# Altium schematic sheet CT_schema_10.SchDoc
size 741 x 377 mm
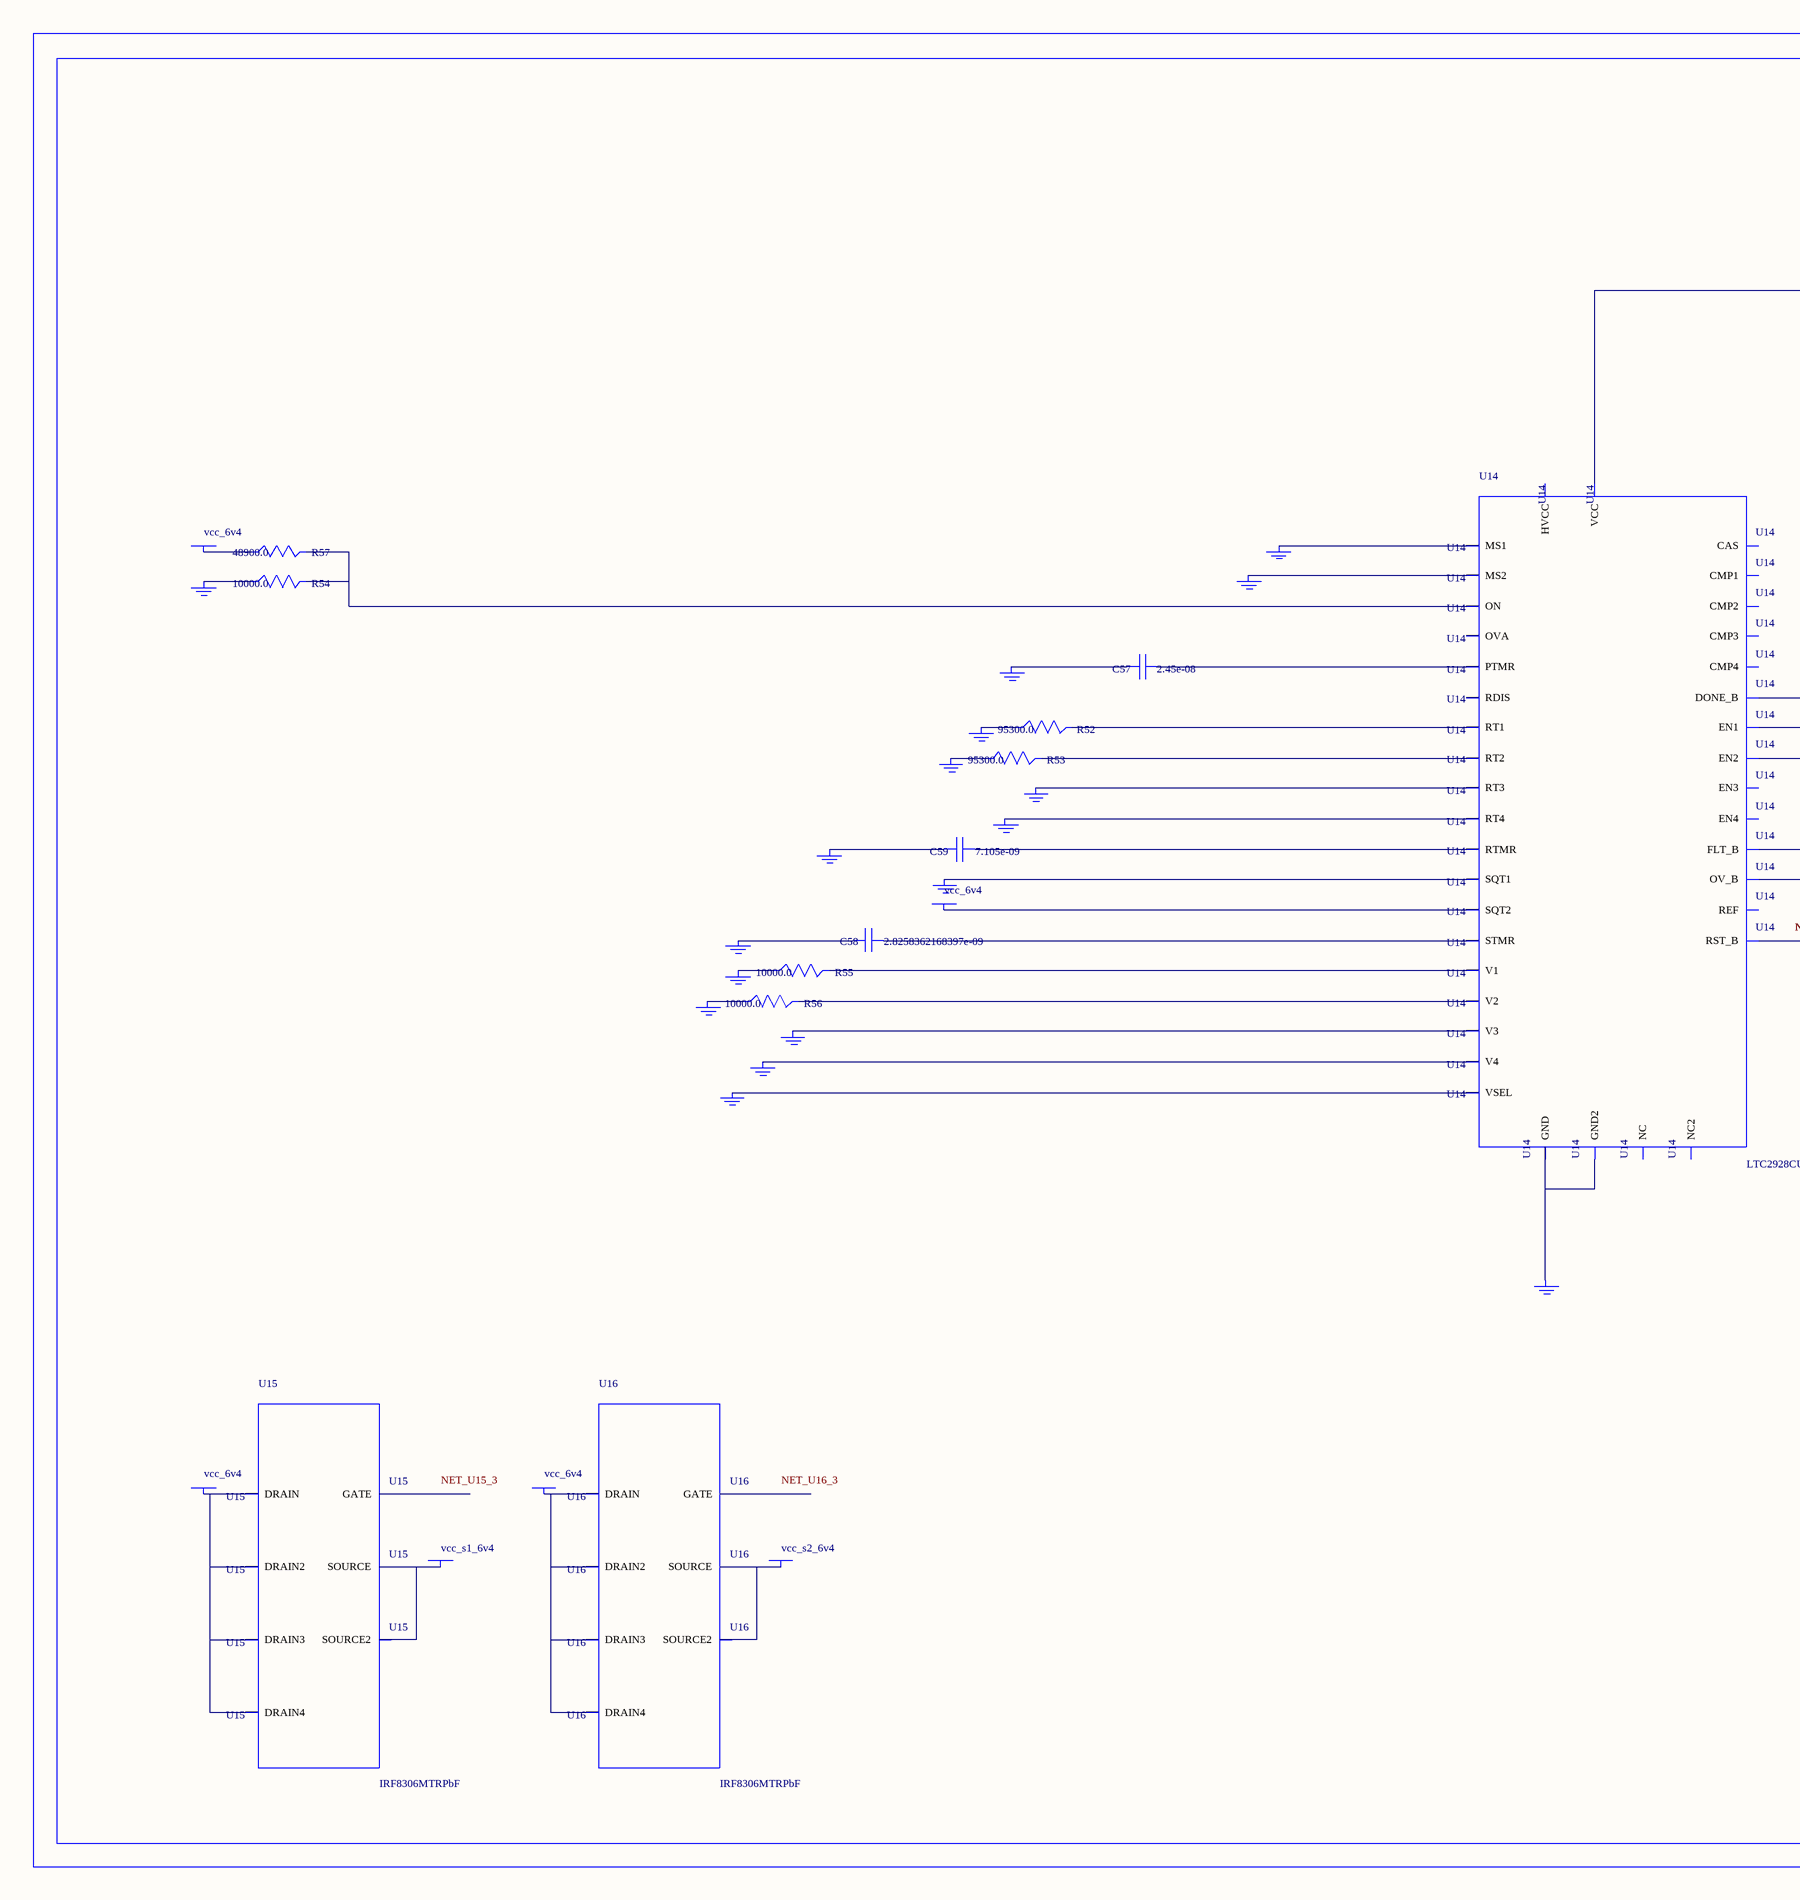
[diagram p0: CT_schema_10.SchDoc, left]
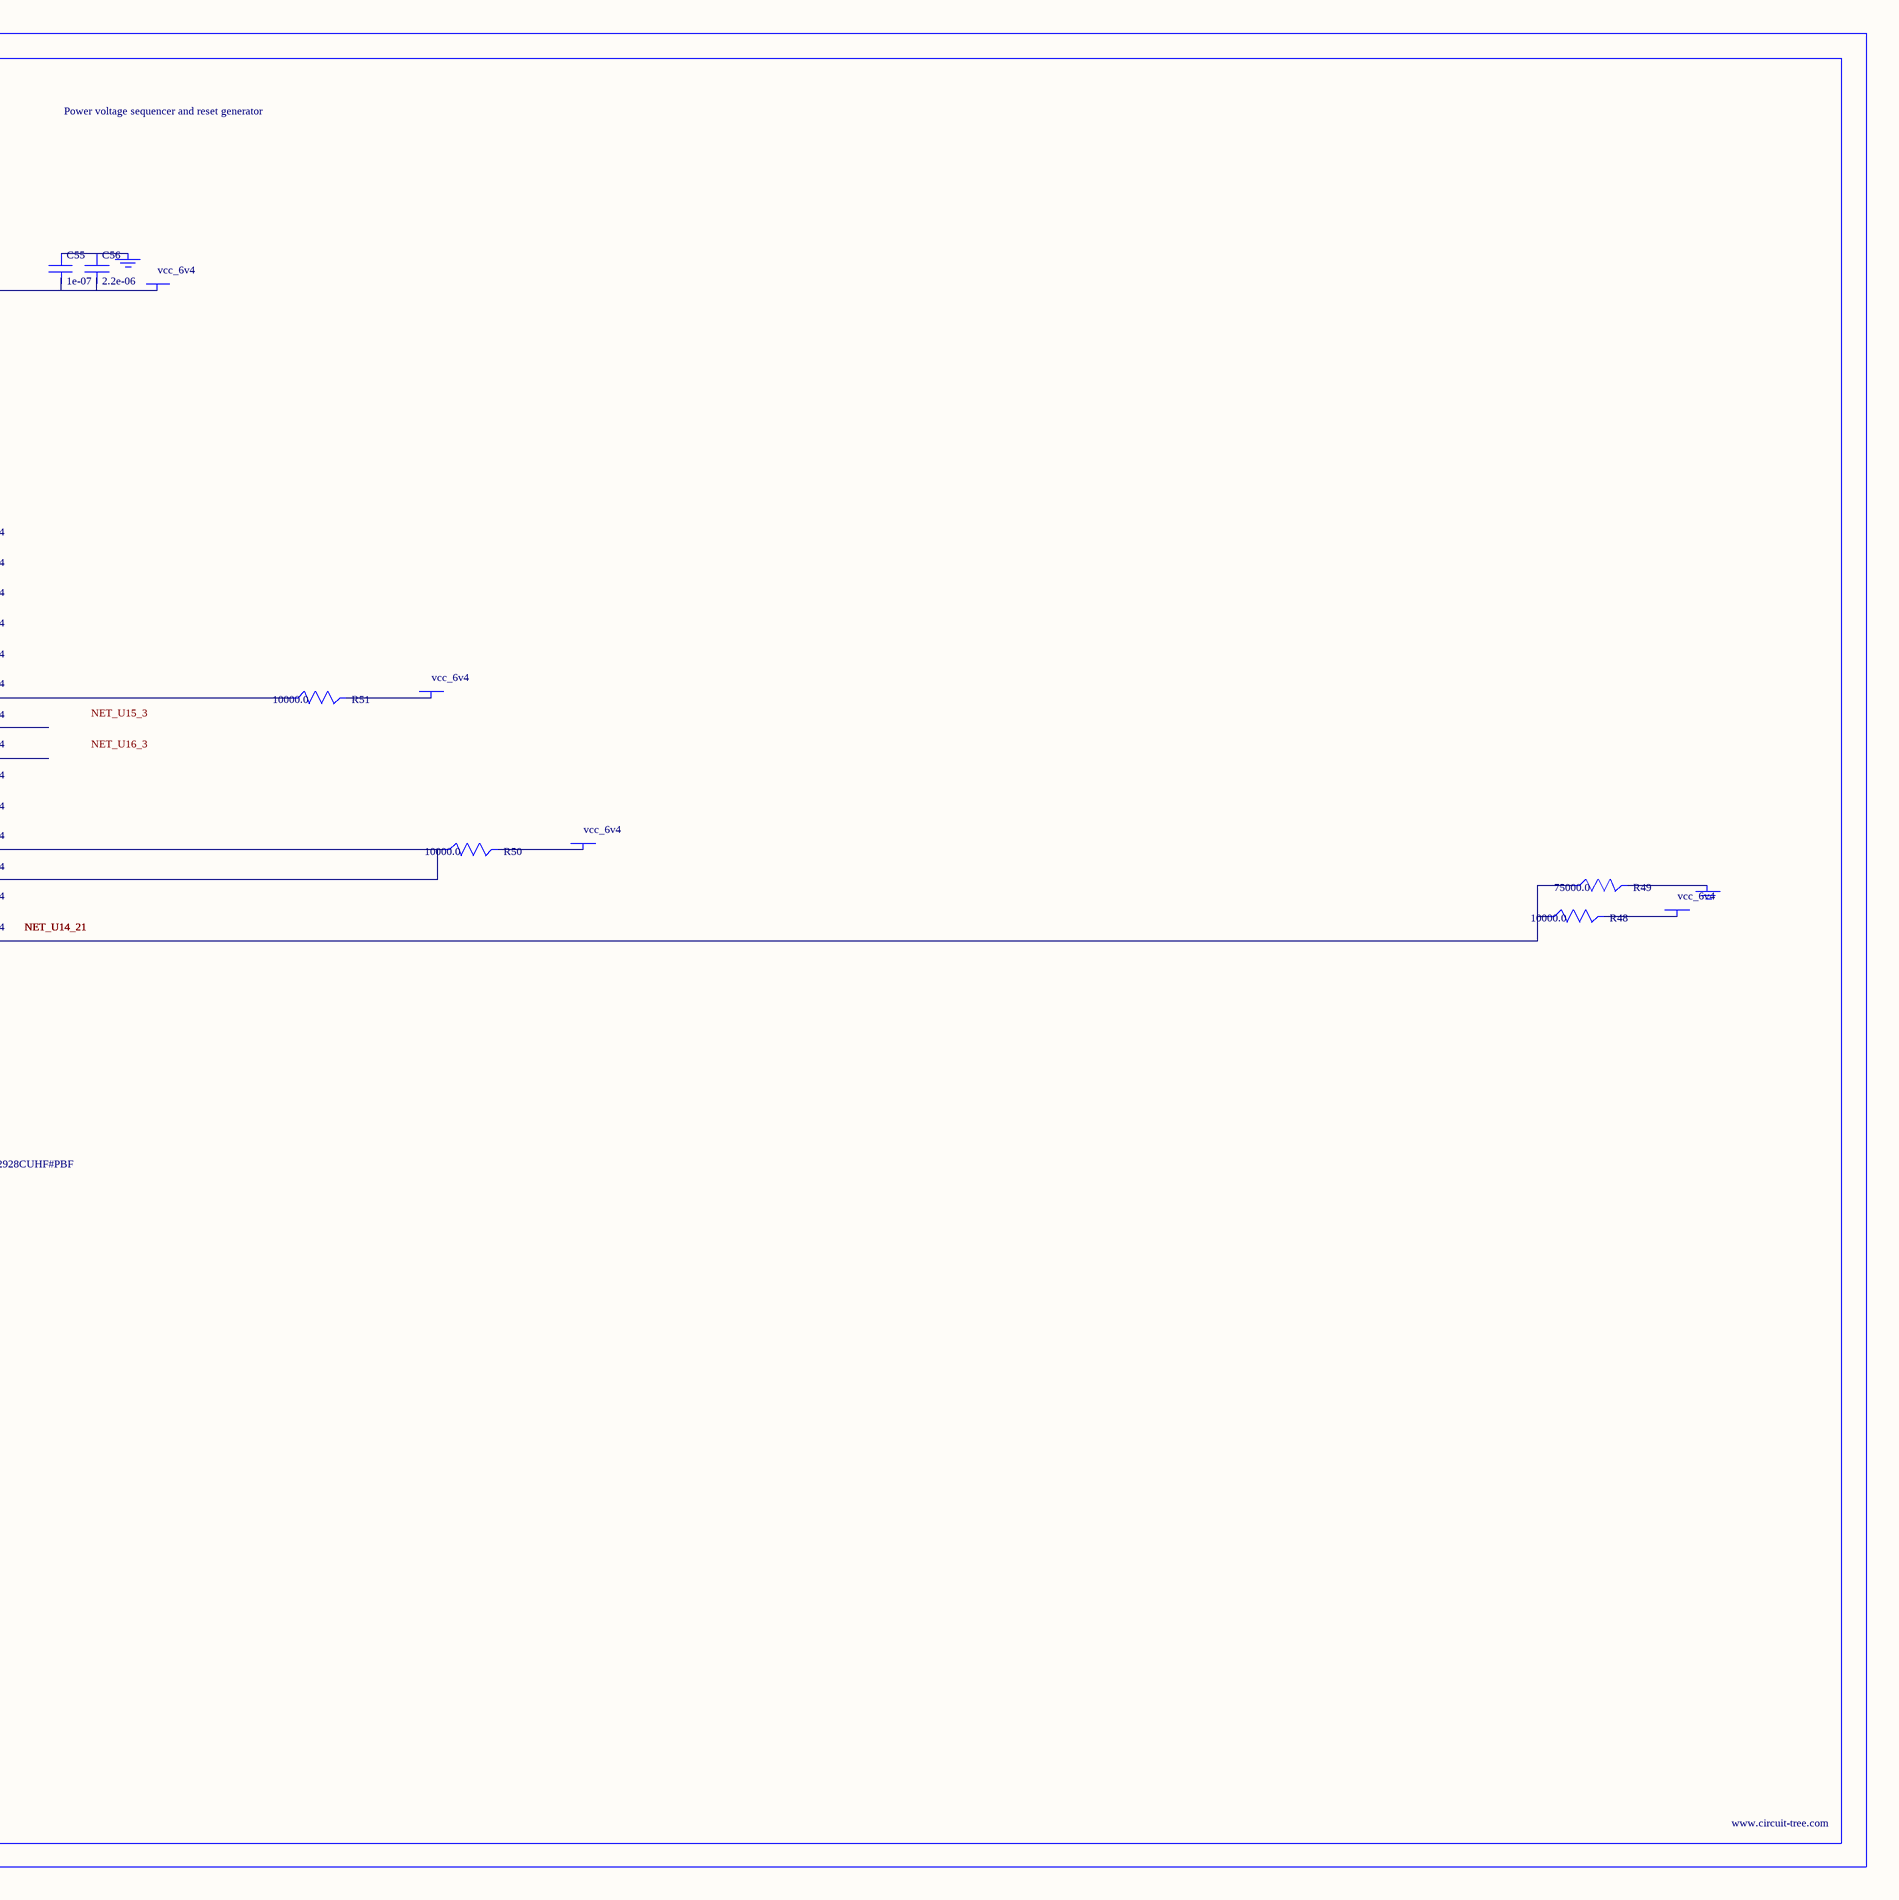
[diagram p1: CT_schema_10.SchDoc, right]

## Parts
BORDER9  (no value)
C55  1e-07  [C0402]
C56  2.2e-06  [C0603]
C57  2.45e-08  [R0603]
C58  2.8258362168397e-09  [R0603]
C59  7.105e-09  [R0603]
GND_INSTANCE_9_0  (no value)
GND_INSTANCE_9_1  (no value)
GND_INSTANCE_9_2  (no value)
GND_INSTANCE_9_3  (no value)
GND_INSTANCE_9_4  (no value)
GND_INSTANCE_9_5  (no value)
GND_INSTANCE_9_6  (no value)
GND_INSTANCE_9_7  (no value)
GND_INSTANCE_9_8  (no value)
GND_INSTANCE_9_9  (no value)
GND_INSTANCE_9_10  (no value)
GND_INSTANCE_9_11  (no value)
GND_INSTANCE_9_12  (no value)
GND_INSTANCE_9_13  (no value)
GND_INSTANCE_9_14  (no value)
GND_INSTANCE_9_15  (no value)
GND_INSTANCE_9_16  (no value)
GND_INSTANCE_9_17  (no value)
GND_INSTANCE_9_18  (no value)
POWER_INSTANCE_9_0  vcc_6v4
POWER_INSTANCE_9_1  vcc_6v4
POWER_INSTANCE_9_2  vcc_6v4
POWER_INSTANCE_9_3  vcc_6v4
POWER_INSTANCE_9_4  vcc_6v4
POWER_INSTANCE_9_5  vcc_6v4
POWER_INSTANCE_9_6  vcc_6v4
POWER_INSTANCE_9_7  vcc_s1_6v4
POWER_INSTANCE_9_8  vcc_6v4
POWER_INSTANCE_9_9  vcc_s2_6v4
R48  10000.0  [R0603]
R49  75000.0  [R0603]
R50  10000.0  [R0603]
R51  10000.0  [R0603]
R52  95300.0  [R0603]
R53  95300.0  [R0603]
R54  10000.0  [R0603]
R55  10000.0  [R0603]
R56  10000.0  [R0603]
R57  48900.0  [R0603]
U14  LTC2928CUHF#PBF  [QFN-38_UHF]
U15  IRF8306MTRPbF  [IRF8306MTRPBF]
U16  IRF8306MTRPbF  [IRF8306MTRPBF]

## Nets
NetC55_1: C55.1 C56.1 GND_INSTANCE_9_10.0(GND)
NetC55_2: C55.2 C56.2 POWER_INSTANCE_9_5.0(PWR) U14.22(VCC)
NetC57_1: C57.1 U14.27(PTMR)
NetC57_2: C57.2 GND_INSTANCE_9_13.0(GND)
NetC58_1: C58.1 U14.26(STMR)
NetC58_2: C58.2 GND_INSTANCE_9_12.0(GND)
NetC59_1: C59.1 U14.28(RTMR)
NetC59_2: C59.2 GND_INSTANCE_9_14.0(GND)
NetGND_INSTANCE_9_0_0: GND_INSTANCE_9_0.0(GND) R55.1
NetGND_INSTANCE_9_1_0: GND_INSTANCE_9_1.0(GND) R52.1
NetGND_INSTANCE_9_2_0: GND_INSTANCE_9_2.0(GND) R53.1
NetGND_INSTANCE_9_3_0: GND_INSTANCE_9_3.0(GND) U14.8(RT3)
NetGND_INSTANCE_9_4_0: GND_INSTANCE_9_4.0(GND) U14.9(RT4)
NetGND_INSTANCE_9_5_0: GND_INSTANCE_9_5.0(GND) U14.10(SQT1)
NetGND_INSTANCE_9_6_0: GND_INSTANCE_9_6.0(GND) U14.12(MS1)
NetGND_INSTANCE_9_7_0: GND_INSTANCE_9_7.0(GND) U14.13(MS2)
NetGND_INSTANCE_9_8_0: GND_INSTANCE_9_8.0(GND) R54.1
NetGND_INSTANCE_9_9_0: GND_INSTANCE_9_9.0(GND) R49.2
NetGND_INSTANCE_9_11_0: GND_INSTANCE_9_11.0(GND) U14.25(VSEL)
NetGND_INSTANCE_9_15_0: GND_INSTANCE_9_15.0(GND) U14.30(V4)
NetGND_INSTANCE_9_16_0: GND_INSTANCE_9_16.0(GND) U14.32(V3)
NetGND_INSTANCE_9_17_0: GND_INSTANCE_9_17.0(GND) R56.1
NetGND_INSTANCE_9_18_0: GND_INSTANCE_9_18.0(GND) U14.24(GND) U14.39(GND2)
NetPOWER_INSTANCE_9_0_0: POWER_INSTANCE_9_0.0(PWR) U14.11(SQT2)
NetPOWER_INSTANCE_9_1_0: POWER_INSTANCE_9_1.0(PWR) R57.1
NetPOWER_INSTANCE_9_2_0: POWER_INSTANCE_9_2.0(PWR) R51.2
NetPOWER_INSTANCE_9_3_0: POWER_INSTANCE_9_3.0(PWR) R50.2
NetPOWER_INSTANCE_9_4_0: POWER_INSTANCE_9_4.0(PWR) R48.2
NetPOWER_INSTANCE_9_6_0: POWER_INSTANCE_9_6.0(PWR) U15.1(DRAIN) U15.2(DRAIN2) U15.6(DRAIN3) U15.7(DRAIN4)
NetPOWER_INSTANCE_9_7_0: POWER_INSTANCE_9_7.0(PWR) U15.4(SOURCE) U15.5(SOURCE2)
NetPOWER_INSTANCE_9_8_0: POWER_INSTANCE_9_8.0(PWR) U16.1(DRAIN) U16.2(DRAIN2) U16.6(DRAIN3) U16.7(DRAIN4)
NetPOWER_INSTANCE_9_9_0: POWER_INSTANCE_9_9.0(PWR) U16.4(SOURCE) U16.5(SOURCE2)
NetR48_1: R48.1 R49.1 U14.21(RST_B)
NetR50_1: R50.1 U14.19(FLT_B) U14.20(OV_B)
NetR51_1: R51.1 U14.18(DONE_B)
NetR52_2: R52.2 U14.6(RT1)
NetR53_2: R53.2 U14.7(RT2)
NetR54_2: R54.2 R57.2 U14.16(ON)
NetR55_2: R55.2 U14.3(V1)
NetR56_2: R56.2 U14.38(V2)

Not connected (* = marked no-connect by the designer): U14 1(OVA) 2(EN1) 4(NC) 5(REF) 14(RDIS) 15(CAS) 17(NC2) 23(HVCC) 29(EN4) 31(EN3) 33(CMP3) 34(CMP4) 35(CMP1) 36(CMP2) 37(EN2); U15 3(GATE); U16 3(GATE)

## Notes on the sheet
- Labels drawn without touching a wire or pin: NET_U15_3, NET_U16_3

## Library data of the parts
BORDER9 = BORDER_PAGE9
C55 = C0402C104K3RACTU
C56 = GRM188R61H225KE1115D
C57 = C57
C58 = C58
C59 = C59
GND_INSTANCE_9_0-GND_INSTANCE_9_18 = GND
POWER_INSTANCE_9_0-POWER_INSTANCE_9_9 = PWR
R48 R50 R51 R54-R56 = RC0603JR-0710KL
R49 = RC0603JR-0775KL
R52 R53 = RC0603FR-0795K3L
R57 = RT0603BRD0745K9L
